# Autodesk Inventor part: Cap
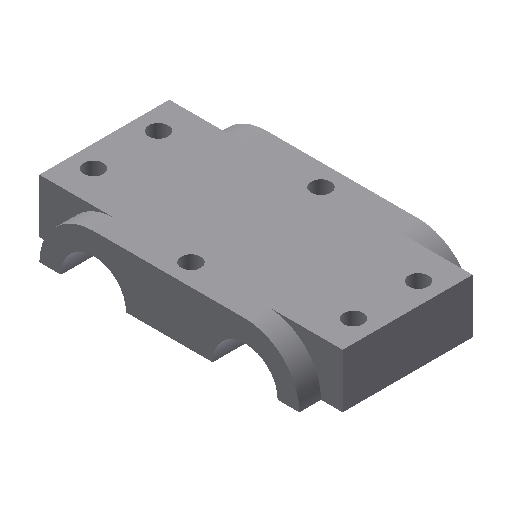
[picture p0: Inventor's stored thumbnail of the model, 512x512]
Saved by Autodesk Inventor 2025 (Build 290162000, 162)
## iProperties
Shininess: 77.0
Length Units: 11269
Angle Units: 11279
Time Units: 11290
Mass Units: 11283
Length Display Precision: 3
Angle Display Precision: 2
Created: 2002-02
Part Number: Cap
Document SubType Name: Modeling
Designer: ***
Density: 1 g/cm^3
Material: Generic
Appearance: Default
Density: 0.0
Volumn: 0.0
Area: 0.0
PropertySet Name: Model Information
Control State: 0
Master: False
Checked Out: False
Author: ***
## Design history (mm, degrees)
sketch "Sketch2"
  geometry: L1 (-17.5, 12.5)-(17.5, 12.5); L2 (30, 0)-(25, 0); L3 (10, 0)-(-10, 0); L4 (-25, 0)-(-30, 0); A1 r 12.5 centre (-17.5, 0) between (-17.5, 12.5) and (-30, 0); A2 r 12.5 centre (17.5, 0) between (30, 0) and (17.5, 12.5); A3 r 7.5 centre (17.5, 0) between (25, 0) and (10, 0); A4 r 7.5 centre (-17.5, 0) between (-10, 0) and (-25, 0)
  constraints: 8 end point, 8 point on circle, 4 centre point, 3 horizontal, 3 parallel, 2 coincident, 2 equal radius, 2 tangent
  dimensions: "d0" = 12.5 radius of A1; "d1" = 7.5 radius of A4; "d2" = 35 distance of A1.centre A2.centre; "d3" = 12.5 distance between parallel lines of L1 L3
extrude "Extrusion1" new body sketch "Sketch2" stored distance "d4" = 40; taper "d5" = 0 deg
workplane "Work Plane1"
sketch "Sketch3"
  geometry: L1 (-15, 12.5)-(15, 12.5); L2 (15, 12.5)-(15, 0); L3 (15, 0)-(-15, 0); L4 (-15, 0)-(-15, 12.5); L5 (-20, 0)-(20, 0) reference; L6 (-20, 12.5)-(20, 12.5) reference; L7 (20, 12.5)-(20, 0) reference
  constraints: 8 end point, 2 collinear, 2 parallel, 1 horizontal, 1 perpendicular
  dimensions: "d7" = 30 distance of L2.end L3.end; "d8" = 5 distance between parallel lines of L7 L2
extrude "Extrusion2" join sketch "Sketch3" stored distance "d9" = 40; taper "d10" = 0 deg
mirror "Mirror1"
sketch "Sketch4"
  geometry: L1 (-17.5, -35)-(0, -35) reference; L2 (-17.5, -35)-(-17.5, -5) reference; 1 further point
  dimensions: "d12" = 7.5 distance from line of L1 point (-12.5, -27.5); "d13" = 5 distance from line of L2 point (-12.5, -27.5)
hole "Hole1" sketch "Sketch4" diameter "d14" = 4.5; stored, may be unused: countersink angle "d18" = 82 deg, drill point angle "d20" = 118 deg; dims "d15" = 6, "d16" = 4, "d17" = 2, "d19" = 8
pattern_linear "Rectangular Pattern1" dims "d26" = 15
sketch "Sketch5"
  geometry: L1 (0, -40)-(35, -40) reference; L2 (-17.5, -35)-(-17.5, -5) reference; 1 further point
  dimensions: "d27" = 5 distance from line of L1 point (17.5, -35); "d28" = 35 distance from line of L2 point (17.5, -35)
hole "Hole2" sketch "Sketch5" diameter "d29" = 4.5; stored, may be unused: countersink angle "d33" = 82 deg, drill point angle "d35" = 118 deg; dims "d30" = 6, "d31" = 4, "d32" = 2, "d34" = 8
pattern_linear "Rectangular Pattern2"
body "Solid1"
other parameters: "d11" = 35
